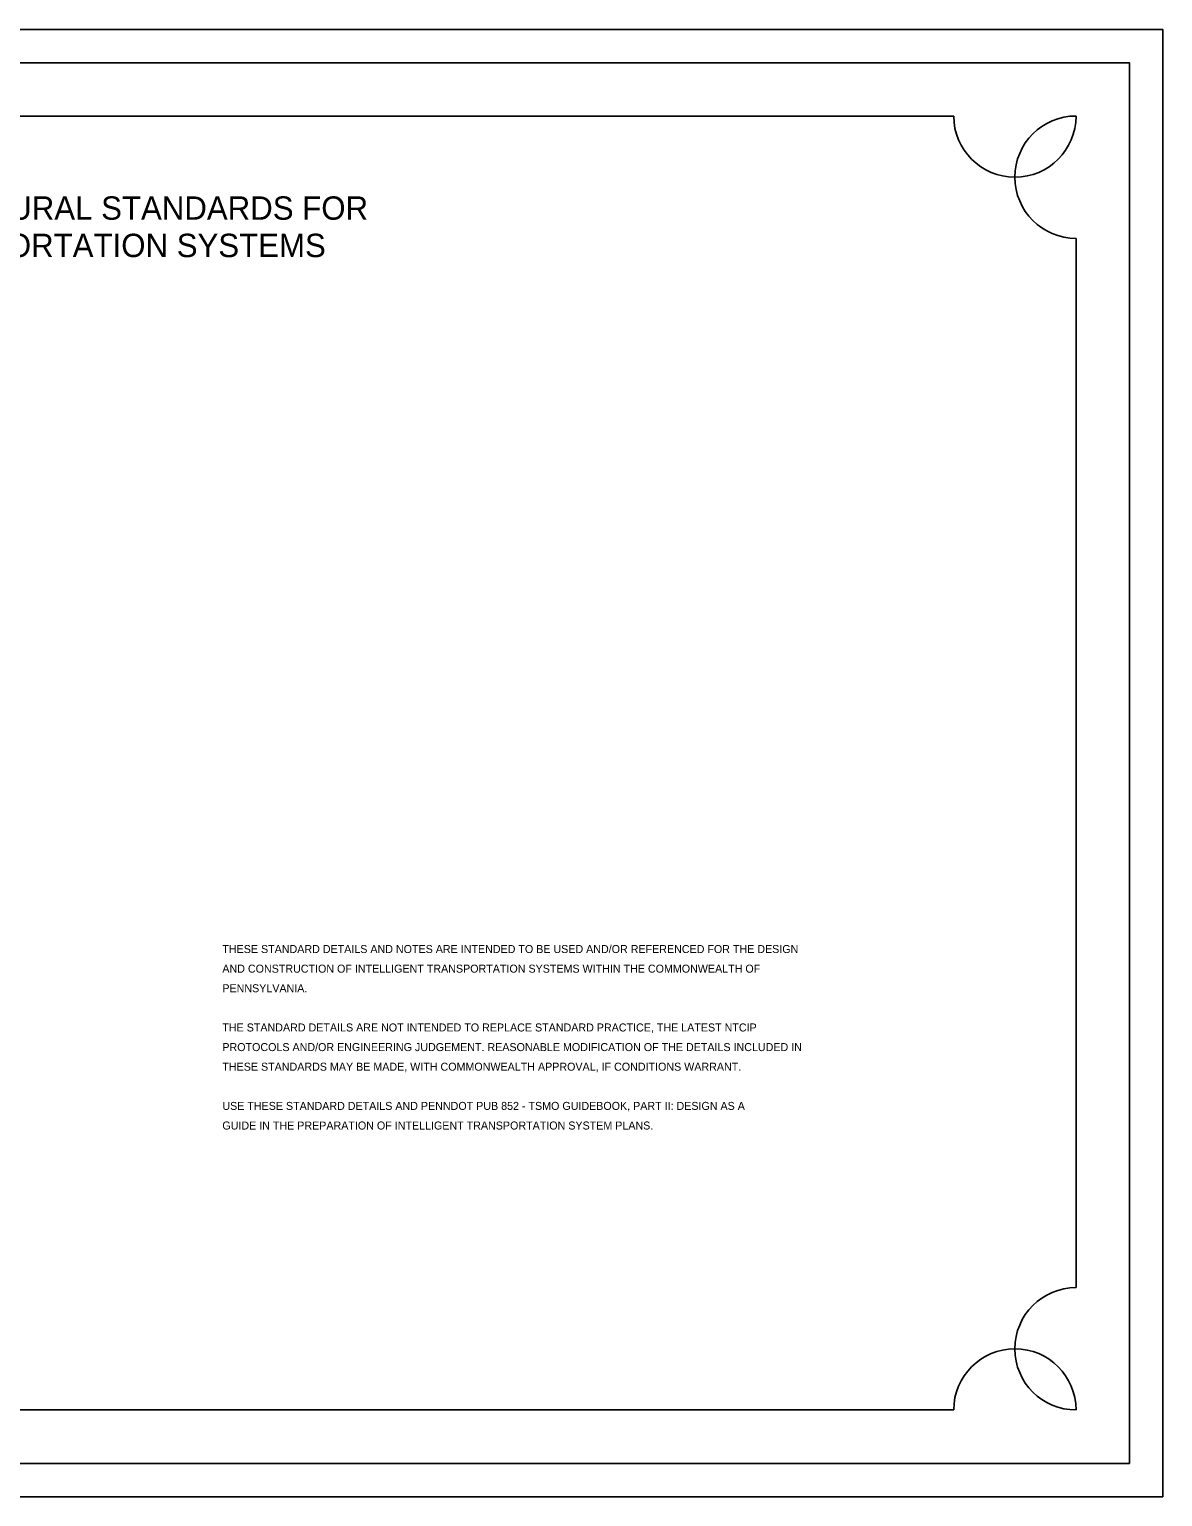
# Model space of a CAD drawing. Extents: x 2558463 to 2558497, y 334216.1 to 334238.1.
# Drawn here: x 2558479.99 to 2558496.99, y 334216.06 to 334238.06 of the extents above; entities that cross this region are included whole.
import ezdxf

# ---------------------------------------------------------------- set-up
doc = ezdxf.new("R2010")
doc.units = 0
for name, color, linetype in [('Default', 7, 'Continuous'), ('DIM TXT', 7, 'Continuous'), ('GS_plotshape_p', 7, 'Continuous'), ('Level 1', 7, 'Continuous'), ('Level 2', 7, 'Continuous')]:
    doc.layers.add(name, color=color, linetype=linetype)

msp = doc.modelspace()

# ---------------------------------------------------------------- linework, layer by layer
at = {"layer": 'Default'}
msp.add_lwpolyline([(2558467.127, 334217.364), (2558493.86, 334217.364)], dxfattribs=at)
at = {"layer": 'GS_plotshape_p'}
msp.add_lwpolyline([(2558462.994, 334238.064), (2558496.994, 334238.064), (2558496.994, 334216.064), (2558462.994, 334216.064)], close=True, dxfattribs=at)
at = {"layer": 'Level 1'}
msp.add_lwpolyline([(2558496.494, 334216.564), (2558464.494, 334216.564), (2558464.494, 334237.564), (2558496.494, 334237.564)], close=True, dxfattribs=at)
at = {"layer": 'Level 2'}
for points in [[(2558493.86, 334236.764), (2558467.127, 334236.764)], [(2558495.694, 334219.198), (2558495.694, 334234.931)]]:
    msp.add_lwpolyline(points, dxfattribs=at)
for centre, start, end in [((2558494.777, 334236.764), 180, 0), ((2558495.694, 334235.848), 90, 270), ((2558495.694, 334218.281), 90, 270), ((2558494.777, 334217.364), 0, 180)]:
    msp.add_arc(centre, 0.917, start, end, dxfattribs=at)

# ---------------------------------------------------------------- texts
at = {"layer": 'DIM TXT'}
for s, p in [('THESE STANDARD DETAILS AND NOTES ARE INTENDED TO BE USED AND/OR REFERENCED FOR THE DESIGN ', (2558482.889, 334224.215)), ('AND CONSTRUCTION OF INTELLIGENT TRANSPORTATION SYSTEMS WITHIN THE COMMONWEALTH OF ', (2558482.889, 334223.921)), ('PENNSYLVANIA. ', (2558482.889, 334223.627)), ('THE STANDARD DETAILS ARE NOT INTENDED TO REPLACE STANDARD PRACTICE, THE LATEST NTCIP ', (2558482.889, 334223.039)), ('PROTOCOLS AND/OR ENGINEERING JUDGEMENT. REASONABLE MODIFICATION OF THE DETAILS INCLUDED IN ', (2558482.889, 334222.745)), ('THESE STANDARDS MAY BE MADE, WITH COMMONWEALTH APPROVAL, IF CONDITIONS WARRANT.', (2558482.889, 334222.451)), ('USE THESE STANDARD DETAILS AND PENNDOT PUB 852 - TSMO GUIDEBOOK, PART II: DESIGN AS A ', (2558482.889, 334221.863)), ('GUIDE IN THE PREPARATION OF INTELLIGENT TRANSPORTATION SYSTEM PLANS. ', (2558482.889, 334221.569))]:
    msp.add_text(s, height=0.12, dxfattribs=at).set_placement(p)
at = {"layer": 'Level 2'}
for s, p in [('INDEX OF CIVIL AND STRUCTURAL STANDARDS FOR', (2558473.035, 334235.21)), ('INTELLIGENT TRANSPORTATION SYSTEMS', (2558474.611, 334234.65))]:
    msp.add_text(s, height=0.35, dxfattribs=at).set_placement(p)

doc.saveas('drawing.dxf')
